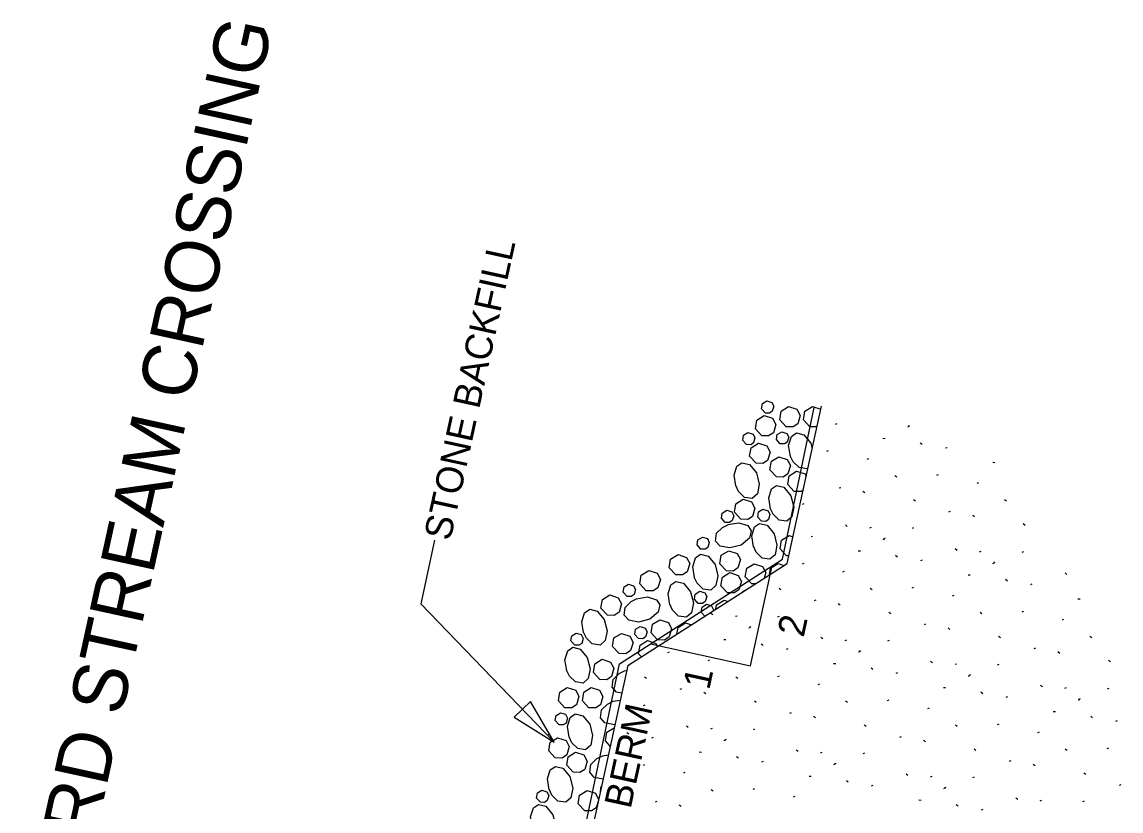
# Model space of a CAD drawing. Extents: x 2126110 to 2128246, y 1804858 to 1811658.
# Drawn here: x 2126689.8 to 2126892.6, y 1806594 to 1806739.6 of the extents above; entities that cross this region are included whole.
import ezdxf

# ---------------------------------------------------------------- set-up
doc = ezdxf.new("R2010")
doc.units = 0
doc.layers.add('1', color=7, linetype='Continuous')

msp = doc.modelspace()

# ---------------------------------------------------------------- linework, layer by layer
at = {"layer": '1'}
for p, q in [((2126830.13, 1806640.44), (2126835.96, 1806668.43)), ((2126830.97, 1806639.65), (2126837.31, 1806668.67)), ((2126839.93, 1806665.39), (2126840.23, 1806665.51)), ((2126853.24, 1806664.89), (2126853.54, 1806665)), ((2126853.37, 1806665.04), (2126853.58, 1806665.12)), ((2126848.65, 1806662.79), (2126849.05, 1806662.75)), ((2126855.89, 1806661.63), (2126855.54, 1806661.88)), ((2126838.34, 1806660.37), (2126838.64, 1806660.49)), ((2126860.2, 1806660.97), (2126860.49, 1806661.08)), ((2126845.78, 1806658.92), (2126846.08, 1806659.03)), ((2126868.91, 1806658.36), (2126869.31, 1806658.32)), ((2126851.2, 1806655.56), (2126850.85, 1806655.82)), ((2126858.61, 1806655.94), (2126858.9, 1806656.06)), ((2126840.58, 1806653.6), (2126840.88, 1806653.71)), ((2126866.04, 1806654.49), (2126866.34, 1806654.61)), ((2126845.31, 1806652.71), (2126844.95, 1806652.97)), ((2126854.64, 1806651.13), (2126854.29, 1806651.39)), ((2126871.46, 1806651.13), (2126871.11, 1806651.39)), ((2126833.83, 1806650.59), (2126834.13, 1806650.71)), ((2126860.84, 1806649.17), (2126861.14, 1806649.29)), ((2126865.57, 1806648.29), (2126865.22, 1806648.54)), ((2126842.09, 1806646.51), (2126841.73, 1806646.77)), ((2126846.24, 1806646.26), (2126846.54, 1806646.38)), ((2126854.09, 1806646.16), (2126854.39, 1806646.28)), ((2126874.91, 1806646.7), (2126874.55, 1806646.96)), ((2126765.94, 1806643.94), (2126763.38, 1806632.22)), ((2126835.39, 1806644.62), (2126835.69, 1806644.73)), ((2126848.7, 1806644.11), (2126849, 1806644.23)), ((2126848.83, 1806644.26), (2126849.13, 1806644.38)), ((2126831.28, 1806641.09), (2126830.9, 1806641.1)), ((2126844.11, 1806642.01), (2126844.51, 1806641.97)), ((2126851.35, 1806640.85), (2126851, 1806641.11)), ((2126862.35, 1806642.08), (2126862, 1806642.34)), ((2126866.5, 1806641.83), (2126866.8, 1806641.95)), ((2126874.35, 1806641.73), (2126874.65, 1806641.85)), ((2126800.03, 1806621.15), (2126830.13, 1806640.44)), ((2126801.61, 1806620.82), (2126830.97, 1806639.65)), ((2126824.21, 1806620.79), (2126828.24, 1806639.23)), ((2126833.8, 1806639.59), (2126834.1, 1806639.71)), ((2126855.65, 1806640.19), (2126855.95, 1806640.31)), ((2126868.96, 1806639.68), (2126869.26, 1806639.8)), ((2126869.1, 1806639.83), (2126869.39, 1806639.95)), ((2126841.24, 1806638.14), (2126841.54, 1806638.25)), ((2126864.37, 1806637.58), (2126864.77, 1806637.54)), ((2126882.61, 1806637.65), (2126882.26, 1806637.91)), ((2126825.08, 1806635.88), (2126824.46, 1806635.89)), ((2126829.84, 1806634.78), (2126829.49, 1806635.04)), ((2126846.66, 1806634.78), (2126846.31, 1806635.04)), ((2126854.07, 1806635.16), (2126854.36, 1806635.28)), ((2126871.62, 1806636.42), (2126871.26, 1806636.68)), ((2126875.92, 1806635.76), (2126876.22, 1806635.88)), ((2126836.04, 1806632.82), (2126836.34, 1806632.93)), ((2126861.5, 1806633.71), (2126861.8, 1806633.83)), ((2126884.63, 1806633.15), (2126885.03, 1806633.11)), ((2126787.99, 1806606.68), (2126763.38, 1806632.22)), ((2126840.76, 1806631.94), (2126840.41, 1806632.19)), ((2126817.28, 1806630.16), (2126816.93, 1806630.42)), ((2126821.44, 1806629.91), (2126821.74, 1806630.03)), ((2126829.29, 1806629.81), (2126829.59, 1806629.93)), ((2126850.1, 1806630.35), (2126849.75, 1806630.61)), ((2126866.92, 1806630.36), (2126866.57, 1806630.61)), ((2126874.33, 1806630.74), (2126874.63, 1806630.85)), ((2126881.76, 1806629.28), (2126882.06, 1806629.4)), ((2126823.89, 1806627.76), (2126824.19, 1806627.88)), ((2126824.03, 1806627.91), (2126824.33, 1806628.03)), ((2126856.3, 1806628.39), (2126856.6, 1806628.51)), ((2126861.03, 1806627.51), (2126860.67, 1806627.77)), ((2126805.76, 1806624.82), (2126824.21, 1806620.79)), ((2126819.3, 1806625.66), (2126819.7, 1806625.62)), ((2126837.55, 1806625.73), (2126837.19, 1806625.99)), ((2126841.7, 1806625.48), (2126842, 1806625.6)), ((2126849.55, 1806625.38), (2126849.85, 1806625.5)), ((2126870.37, 1806625.92), (2126870.01, 1806626.18)), ((2126887.18, 1806625.93), (2126886.83, 1806626.19)), ((2126809, 1806623.24), (2126809.3, 1806623.36)), ((2126826.55, 1806624.5), (2126826.2, 1806624.76)), ((2126830.85, 1806623.84), (2126831.15, 1806623.95)), ((2126844.16, 1806623.33), (2126844.45, 1806623.45)), ((2126844.29, 1806623.48), (2126844.59, 1806623.6)), ((2126876.57, 1806623.96), (2126876.87, 1806624.08)), ((2126881.29, 1806623.08), (2126880.94, 1806623.34)), ((2126793.9, 1806591.8), (2126800.03, 1806621.15)), ((2126801.61, 1806620.82), (2126795.26, 1806591.77)), ((2126816.44, 1806621.79), (2126816.73, 1806621.9)), ((2126839.57, 1806621.23), (2126839.97, 1806621.19)), ((2126857.81, 1806621.3), (2126857.46, 1806621.56)), ((2126861.96, 1806621.06), (2126862.26, 1806621.17)), ((2126869.81, 1806620.96), (2126870.11, 1806621.07)), ((2126890.63, 1806621.49), (2126890.28, 1806621.75)), ((2126801, 1806619.88), (2126801.42, 1806619.94)), ((2126829.26, 1806618.81), (2126829.56, 1806618.93)), ((2126846.81, 1806620.07), (2126846.46, 1806620.33)), ((2126851.11, 1806619.41), (2126851.41, 1806619.53)), ((2126864.42, 1806618.9), (2126864.72, 1806619.02)), ((2126864.56, 1806619.06), (2126864.85, 1806619.17)), ((2126805.04, 1806618.43), (2126804.69, 1806618.69)), ((2126821.86, 1806618.43), (2126821.5, 1806618.69)), ((2126836.7, 1806617.36), (2126837, 1806617.48)), ((2126859.83, 1806616.8), (2126860.23, 1806616.76)), ((2126878.07, 1806616.88), (2126877.72, 1806617.13)), ((2126882.23, 1806616.63), (2126882.53, 1806616.75)), ((2126811.24, 1806616.47), (2126811.54, 1806616.58)), ((2126815.96, 1806615.58), (2126815.61, 1806615.84)), ((2126867.08, 1806615.64), (2126866.72, 1806615.9)), ((2126871.38, 1806614.98), (2126871.68, 1806615.1)), ((2126884.82, 1806614.63), (2126885.12, 1806614.74)), ((2126890.08, 1806616.53), (2126890.37, 1806616.64)), ((2126798.83, 1806614.23), (2126800.22, 1806614.46)), ((2126804.48, 1806613.46), (2126804.78, 1806613.58)), ((2126825.3, 1806614), (2126824.95, 1806614.26)), ((2126842.12, 1806614), (2126841.77, 1806614.26)), ((2126849.52, 1806614.39), (2126849.82, 1806614.5)), ((2126856.96, 1806612.93), (2126857.26, 1806613.05)), ((2126884.68, 1806614.48), (2126884.98, 1806614.59)), ((2126831.5, 1806612.04), (2126831.8, 1806612.16)), ((2126836.22, 1806611.16), (2126835.87, 1806611.42)), ((2126880.09, 1806612.38), (2126880.49, 1806612.33)), ((2126887.34, 1806611.21), (2126886.99, 1806611.47)), ((2126891.64, 1806610.55), (2126891.94, 1806610.67)), ((2126812.74, 1806609.38), (2126812.39, 1806609.64)), ((2126816.9, 1806609.13), (2126817.2, 1806609.25)), ((2126824.75, 1806609.03), (2126825.05, 1806609.15)), ((2126845.56, 1806609.57), (2126845.21, 1806609.83)), ((2126862.38, 1806609.58), (2126862.03, 1806609.84)), ((2126869.79, 1806609.96), (2126870.09, 1806610.08)), ((2126877.22, 1806608.5), (2126877.52, 1806608.62)), ((2126801.75, 1806608.15), (2126801.39, 1806608.4)), ((2126806.05, 1806607.49), (2126806.35, 1806607.6)), ((2126819.35, 1806606.98), (2126819.65, 1806607.1)), ((2126819.49, 1806607.13), (2126819.79, 1806607.25)), ((2126851.76, 1806607.61), (2126852.06, 1806607.73)), ((2126856.49, 1806606.73), (2126856.13, 1806606.99)), ((2126814.76, 1806604.88), (2126815.16, 1806604.84)), ((2126833, 1806604.95), (2126832.65, 1806605.21)), ((2126837.16, 1806604.71), (2126837.46, 1806604.82)), ((2126845.01, 1806604.6), (2126845.31, 1806604.72)), ((2126865.83, 1806605.14), (2126865.47, 1806605.4)), ((2126882.64, 1806605.15), (2126882.29, 1806605.41)), ((2126890.05, 1806605.53), (2126890.35, 1806605.65)), ((2126796.88, 1806604.16), (2126798.01, 1806604.35)), ((2126804.46, 1806602.46), (2126804.76, 1806602.58)), ((2126822.01, 1806603.72), (2126821.66, 1806603.98)), ((2126826.31, 1806603.06), (2126826.61, 1806603.18)), ((2126839.62, 1806602.55), (2126839.91, 1806602.67)), ((2126839.75, 1806602.7), (2126840.05, 1806602.82)), ((2126872.03, 1806603.18), (2126872.32, 1806603.3)), ((2126876.75, 1806602.3), (2126876.4, 1806602.56)), ((2126811.9, 1806601.01), (2126812.19, 1806601.13)), ((2126853.27, 1806600.52), (2126852.92, 1806600.78)), ((2126886.09, 1806600.72), (2126885.74, 1806600.97)), ((2126835.03, 1806600.45), (2126835.43, 1806600.41)), ((2126842.27, 1806599.29), (2126841.92, 1806599.55)), ((2126846.57, 1806598.63), (2126846.87, 1806598.75)), ((2126857.42, 1806600.28), (2126857.72, 1806600.39)), ((2126865.27, 1806600.18), (2126865.57, 1806600.29)), ((2126892.29, 1806598.76), (2126892.59, 1806598.87)), ((2126800.5, 1806597.65), (2126800.15, 1806597.91)), ((2126817.32, 1806597.65), (2126816.96, 1806597.91)), ((2126824.72, 1806598.04), (2126825.02, 1806598.15)), ((2126832.16, 1806596.58), (2126832.46, 1806596.7)), ((2126859.88, 1806598.13), (2126860.18, 1806598.24)), ((2126860.02, 1806598.28), (2126860.31, 1806598.39)), ((2126806.7, 1806595.69), (2126807, 1806595.81)), ((2126811.42, 1806594.81), (2126811.07, 1806595.07)), ((2126855.29, 1806596.03), (2126855.69, 1806595.98)), ((2126862.53, 1806594.86), (2126862.18, 1806595.12)), ((2126873.53, 1806596.1), (2126873.18, 1806596.36)), ((2126877.69, 1806595.85), (2126877.98, 1806595.97)), ((2126885.53, 1806595.75), (2126885.83, 1806595.87)), ((2126866.84, 1806594.2), (2126867.13, 1806594.32))]:
    msp.add_line(p, q, dxfattribs=at)
for points in [[(2126826.97, 1806667.42), (2126826.26, 1806668.19), (2126826.41, 1806669.15), (2126827.23, 1806669.66), (2126828.16, 1806669.35), (2126828.52, 1806668.66), (2126828.25, 1806667.75), (2126827.73, 1806667.4), (2126826.97, 1806667.42)], [(2126830.8, 1806664.89), (2126829.61, 1806666.18), (2126829.87, 1806667.77), (2126831.24, 1806668.62), (2126832.79, 1806668.11), (2126833.39, 1806666.96), (2126832.94, 1806665.43), (2126832.07, 1806664.86), (2126830.8, 1806664.89)], [(2126835.2, 1806664.9), (2126834.01, 1806666.19), (2126834.26, 1806667.78), (2126835.64, 1806668.63), (2126837.19, 1806668.12), (2126837.19, 1806668.12)], [(2126826.3, 1806663.24), (2126825.12, 1806664.53), (2126825.37, 1806666.13), (2126826.74, 1806666.97), (2126828.3, 1806666.47), (2126828.89, 1806665.32), (2126828.44, 1806663.79), (2126827.57, 1806663.21), (2126826.3, 1806663.24)], [(2126823.5, 1806661.59), (2126822.79, 1806662.37), (2126822.94, 1806663.32), (2126823.76, 1806663.83), (2126824.7, 1806663.53), (2126825.05, 1806662.84), (2126824.78, 1806661.92), (2126824.26, 1806661.58), (2126823.5, 1806661.59)], [(2126829.73, 1806661.74), (2126829.02, 1806662.51), (2126829.17, 1806663.47), (2126829.99, 1806663.98), (2126830.93, 1806663.67), (2126831.28, 1806662.98), (2126831.01, 1806662.07), (2126830.49, 1806661.72), (2126829.73, 1806661.74)], [(2126831.58, 1806659.44), (2126831.25, 1806661.45), (2126831.77, 1806663.11), (2126832.71, 1806663.75), (2126834.08, 1806663.42), (2126835.37, 1806661.86), (2126835.61, 1806660.91)], [(2126836.48, 1806664.88), (2126836.47, 1806664.87), (2126835.2, 1806664.9)], [(2126825.25, 1806658.15), (2126824.06, 1806659.44), (2126824.32, 1806661.03), (2126825.69, 1806661.88), (2126827.24, 1806661.37), (2126827.84, 1806660.22), (2126827.39, 1806658.69), (2126826.52, 1806658.12), (2126825.25, 1806658.15)], [(2126829, 1806655.63), (2126827.81, 1806656.93), (2126828.07, 1806658.52), (2126829.44, 1806659.36), (2126830.99, 1806658.86), (2126831.59, 1806657.71), (2126831.14, 1806656.18), (2126830.27, 1806655.61), (2126829, 1806655.63)], [(2126834.83, 1806657.33), (2126834.62, 1806657.13), (2126833.18, 1806657.35), (2126832.09, 1806658.44), (2126831.55, 1806659.53)], [(2126821.52, 1806653.96), (2126821.2, 1806655.96), (2126821.71, 1806657.62), (2126822.65, 1806658.26), (2126824.02, 1806657.93), (2126825.32, 1806656.37), (2126825.85, 1806654.28), (2126825.49, 1806652.49), (2126824.56, 1806651.65), (2126823.12, 1806651.86), (2126822.03, 1806652.95), (2126821.49, 1806654.04)], [(2126832.3, 1806652.97), (2126831.12, 1806654.26), (2126831.37, 1806655.85), (2126832.74, 1806656.7), (2126834.3, 1806656.19), (2126834.5, 1806655.8)], [(2126827.9, 1806649.76), (2126827.58, 1806651.76), (2126828.09, 1806653.42), (2126829.03, 1806654.06), (2126830.4, 1806653.73), (2126831.69, 1806652.17), (2126832.23, 1806650.08), (2126831.87, 1806648.29), (2126830.94, 1806647.45), (2126829.5, 1806647.66), (2126828.41, 1806648.75), (2126827.87, 1806649.84)], [(2126822.44, 1806647.81), (2126821.26, 1806649.1), (2126821.51, 1806650.69), (2126822.88, 1806651.54), (2126824.44, 1806651.03), (2126825.03, 1806649.88), (2126824.58, 1806648.35), (2126823.71, 1806647.78), (2126822.44, 1806647.81)], [(2126833.92, 1806653.18), (2126833.57, 1806652.94), (2126832.3, 1806652.97)], [(2126819.57, 1806647.24), (2126818.86, 1806648.01), (2126819.01, 1806648.97), (2126819.83, 1806649.48), (2126820.76, 1806649.17), (2126821.12, 1806648.48), (2126820.85, 1806647.57), (2126820.33, 1806647.22), (2126819.57, 1806647.24)], [(2126826.27, 1806647.44), (2126825.55, 1806648.22), (2126825.71, 1806649.17), (2126826.53, 1806649.68), (2126827.46, 1806649.38), (2126827.82, 1806648.69), (2126827.55, 1806647.77), (2126827.03, 1806647.42), (2126826.27, 1806647.44)], [(2126820.07, 1806646.84), (2126822.07, 1806647.17), (2126823.73, 1806646.65), (2126824.37, 1806645.71), (2126824.04, 1806644.34), (2126822.48, 1806643.05), (2126820.39, 1806642.52), (2126818.6, 1806642.87), (2126817.75, 1806643.8), (2126817.97, 1806645.24), (2126819.06, 1806646.33), (2126820.15, 1806646.87)], [(2126824.79, 1806642.75), (2126824.46, 1806644.75), (2126824.97, 1806646.41), (2126825.91, 1806647.05), (2126827.28, 1806646.72), (2126828.58, 1806645.16), (2126829.11, 1806643.07), (2126828.75, 1806641.28), (2126827.82, 1806640.43), (2126826.38, 1806640.65), (2126825.29, 1806641.74), (2126824.75, 1806642.83)], [(2126815.07, 1806642.3), (2126814.36, 1806643.08), (2126814.51, 1806644.03), (2126815.34, 1806644.54), (2126816.27, 1806644.24), (2126816.63, 1806643.55), (2126816.36, 1806642.63), (2126815.84, 1806642.29), (2126815.08, 1806642.3)], [(2126830.89, 1806641.1), (2126829.71, 1806642.39), (2126829.96, 1806643.98), (2126831.33, 1806644.83), (2126832.05, 1806644.6)], [(2126810.43, 1806637.57), (2126809.24, 1806638.86), (2126809.49, 1806640.45), (2126810.87, 1806641.3), (2126812.42, 1806640.79), (2126813.02, 1806639.65), (2126812.57, 1806638.12), (2126811.7, 1806637.54), (2126810.43, 1806637.57)], [(2126813.9, 1806637.05), (2126813.57, 1806639.05), (2126814.08, 1806640.71), (2126815.02, 1806641.35), (2126816.39, 1806641.02), (2126817.69, 1806639.46), (2126818.22, 1806637.37), (2126817.86, 1806635.58), (2126816.93, 1806634.73), (2126815.49, 1806634.95), (2126814.4, 1806636.04), (2126813.86, 1806637.13)], [(2126819.77, 1806638.29), (2126818.59, 1806639.58), (2126818.84, 1806641.17), (2126820.21, 1806642.02), (2126821.77, 1806641.52), (2126822.36, 1806640.37), (2126821.91, 1806638.84), (2126821.04, 1806638.26), (2126819.77, 1806638.29)], [(2126824.46, 1806635.89), (2126823.27, 1806637.18), (2126823.53, 1806638.77), (2126824.9, 1806639.62), (2126826.46, 1806639.11), (2126827.05, 1806637.97), (2126826.75, 1806636.95)], [(2126827.73, 1806637.58), (2126827.93, 1806638.78), (2126829.3, 1806639.63), (2126830.38, 1806639.28)], [(2126805, 1806634.63), (2126803.81, 1806635.92), (2126804.06, 1806637.51), (2126805.44, 1806638.36), (2126806.99, 1806637.85), (2126807.59, 1806636.7), (2126807.14, 1806635.17), (2126806.27, 1806634.6), (2126805, 1806634.63)], [(2126819.96, 1806634.25), (2126818.78, 1806635.54), (2126819.03, 1806637.13), (2126820.41, 1806637.98), (2126821.96, 1806637.47), (2126822.56, 1806636.32), (2126822.1, 1806634.79), (2126821.24, 1806634.22), (2126819.97, 1806634.25)], [(2126801.46, 1806633.6), (2126800.75, 1806634.37), (2126800.9, 1806635.33), (2126801.72, 1806635.84), (2126802.65, 1806635.53), (2126803.01, 1806634.85), (2126802.74, 1806633.93), (2126802.22, 1806633.58), (2126801.46, 1806633.6)], [(2126809.35, 1806632.05), (2126809.03, 1806634.05), (2126809.54, 1806635.71), (2126810.48, 1806636.35), (2126811.85, 1806636.02), (2126813.15, 1806634.46), (2126813.68, 1806632.37), (2126813.32, 1806630.58), (2126812.39, 1806629.74), (2126810.95, 1806629.95), (2126809.86, 1806631.04), (2126809.32, 1806632.13)], [(2126822.83, 1806634.43), (2126822.83, 1806634.47), (2126823.66, 1806634.98), (2126823.67, 1806634.97)], [(2126797.83, 1806630.12), (2126796.64, 1806631.41), (2126796.9, 1806633.01), (2126798.27, 1806633.85), (2126799.82, 1806633.35), (2126800.42, 1806632.2), (2126799.97, 1806630.67), (2126799.1, 1806630.09), (2126797.83, 1806630.12)], [(2126803.22, 1806633.16), (2126805.22, 1806633.49), (2126806.88, 1806632.97), (2126807.52, 1806632.03), (2126807.19, 1806630.66), (2126805.63, 1806629.37), (2126803.54, 1806628.84), (2126801.75, 1806629.2), (2126800.9, 1806630.13), (2126801.12, 1806631.56), (2126802.21, 1806632.65), (2126803.3, 1806633.19)], [(2126814.58, 1806632.29), (2126813.87, 1806633.07), (2126814.02, 1806634.03), (2126814.85, 1806634.53), (2126815.78, 1806634.23), (2126816.14, 1806633.54), (2126815.86, 1806632.62), (2126815.34, 1806632.28), (2126814.58, 1806632.3)], [(2126793.43, 1806626.91), (2126793.1, 1806628.91), (2126793.62, 1806630.57), (2126794.56, 1806631.21), (2126795.93, 1806630.88), (2126797.22, 1806629.32), (2126797.76, 1806627.23), (2126797.4, 1806625.44), (2126796.47, 1806624.6), (2126795.03, 1806624.81), (2126793.94, 1806625.9), (2126793.4, 1806626.99)], [(2126815.81, 1806629.93), (2126815.13, 1806630.66), (2126815.29, 1806631.62), (2126816.11, 1806632.13), (2126817.04, 1806631.82), (2126817.4, 1806631.13), (2126817.33, 1806630.91)], [(2126817.85, 1806631.24), (2126817.98, 1806632.03), (2126819.35, 1806632.88), (2126820.05, 1806632.65)], [(2126807.07, 1806625.56), (2126805.89, 1806626.85), (2126806.14, 1806628.44), (2126807.51, 1806629.29), (2126809.07, 1806628.78), (2126809.66, 1806627.63), (2126809.21, 1806626.1), (2126808.34, 1806625.53), (2126807.07, 1806625.56)], [(2126791.8, 1806624.59), (2126791.08, 1806625.37), (2126791.24, 1806626.32), (2126792.06, 1806626.83), (2126792.99, 1806626.53), (2126793.35, 1806625.84), (2126793.08, 1806624.92), (2126792.56, 1806624.58), (2126791.8, 1806624.59)], [(2126803.58, 1806625.79), (2126802.87, 1806626.57), (2126803.02, 1806627.52), (2126803.84, 1806628.03), (2126804.77, 1806627.73), (2126805.13, 1806627.04), (2126804.86, 1806626.12), (2126804.34, 1806625.78), (2126803.58, 1806625.79)], [(2126810.65, 1806626.62), (2126810.85, 1806627.87), (2126812.22, 1806628.72), (2126813.35, 1806628.35)], [(2126799.97, 1806623.04), (2126798.78, 1806624.33), (2126799.03, 1806625.92), (2126800.41, 1806626.77), (2126801.96, 1806626.26), (2126802.56, 1806625.11), (2126802.11, 1806623.58), (2126801.24, 1806623.01), (2126799.97, 1806623.04)], [(2126804.11, 1806622.42), (2126803.59, 1806622.99), (2126803.84, 1806624.58), (2126805.21, 1806625.43), (2126806.77, 1806624.92), (2126807.07, 1806624.33)], [(2126790.31, 1806619.9), (2126789.99, 1806621.9), (2126790.5, 1806623.56), (2126791.44, 1806624.2), (2126792.81, 1806623.87), (2126794.11, 1806622.31), (2126794.64, 1806620.22), (2126794.28, 1806618.43), (2126793.35, 1806617.59), (2126791.91, 1806617.8), (2126790.82, 1806618.89), (2126790.28, 1806619.98)], [(2126796.42, 1806618.25), (2126795.24, 1806619.54), (2126795.49, 1806621.13), (2126796.86, 1806621.98), (2126798.42, 1806621.47), (2126799.01, 1806620.33), (2126798.56, 1806618.8), (2126797.69, 1806618.22), (2126796.42, 1806618.25)], [(2126800.49, 1806615.72), (2126799.53, 1806615.91), (2126798.69, 1806616.84), (2126798.9, 1806618.28), (2126799.99, 1806619.37), (2126801.08, 1806619.91)], [(2126789.99, 1806613.04), (2126788.8, 1806614.33), (2126789.06, 1806615.93), (2126790.43, 1806616.77), (2126791.98, 1806616.27), (2126792.58, 1806615.12), (2126792.13, 1806613.59), (2126791.26, 1806613.01), (2126789.99, 1806613.04)], [(2126794.39, 1806613.05), (2126793.2, 1806614.34), (2126793.46, 1806615.94), (2126794.83, 1806616.78), (2126796.38, 1806616.28), (2126796.98, 1806615.13), (2126796.53, 1806613.6), (2126795.66, 1806613.02), (2126794.39, 1806613.05)], [(2126799.23, 1806609.93), (2126799.15, 1806609.91), (2126797.36, 1806610.26), (2126796.52, 1806611.19), (2126796.73, 1806612.63), (2126797.82, 1806613.72), (2126798.91, 1806614.26)], [(2126788.92, 1806609.89), (2126788.21, 1806610.67), (2126788.36, 1806611.62), (2126789.19, 1806612.13), (2126790.12, 1806611.83), (2126790.48, 1806611.14), (2126790.2, 1806610.22), (2126789.68, 1806609.88), (2126788.92, 1806609.89)], [(2126790.77, 1806607.6), (2126790.45, 1806609.6), (2126790.96, 1806611.26), (2126791.9, 1806611.9), (2126793.27, 1806611.58), (2126794.56, 1806610.01), (2126795.1, 1806607.92), (2126794.74, 1806606.13), (2126793.81, 1806605.29), (2126792.37, 1806605.5), (2126791.28, 1806606.59), (2126790.74, 1806607.69)], [(2126798.36, 1806605.96), (2126797.47, 1806606.92), (2126797.73, 1806608.51), (2126799.1, 1806609.36), (2126799.1, 1806609.36)], [(2126787.01, 1806608.41), (2126787.03, 1806608.38), (2126786.93, 1806608.03)], [(2126788.19, 1806603.79), (2126787.01, 1806605.08), (2126787.26, 1806606.67), (2126788.63, 1806607.52), (2126790.19, 1806607.01), (2126790.78, 1806605.87), (2126790.33, 1806604.34), (2126789.46, 1806603.76), (2126788.19, 1806603.79)], [(2126791.49, 1806601.13), (2126790.31, 1806602.42), (2126790.56, 1806604.01), (2126791.93, 1806604.86), (2126793.49, 1806604.35), (2126794.08, 1806603.2), (2126793.63, 1806601.67), (2126792.76, 1806601.1), (2126791.49, 1806601.13)], [(2126797.03, 1806599.88), (2126795.41, 1806600.2), (2126794.57, 1806601.13), (2126794.78, 1806602.57), (2126795.87, 1806603.66), (2126796.96, 1806604.2)], [(2126787.1, 1806597.91), (2126786.77, 1806599.92), (2126787.28, 1806601.58), (2126788.22, 1806602.21), (2126789.59, 1806601.89), (2126790.89, 1806600.33), (2126791.42, 1806598.23), (2126791.06, 1806596.45), (2126790.13, 1806595.6), (2126788.69, 1806595.82), (2126787.6, 1806596.91), (2126787.06, 1806598)], [(2126796.54, 1806597.62), (2126796.68, 1806598.53), (2126796.74, 1806598.57)], [(2126785.46, 1806595.6), (2126784.75, 1806596.37), (2126784.9, 1806597.33), (2126785.72, 1806597.83), (2126786.66, 1806597.53), (2126787.01, 1806596.84), (2126786.74, 1806595.92), (2126786.22, 1806595.58), (2126785.46, 1806595.6)], [(2126793.63, 1806594.04), (2126792.44, 1806595.33), (2126792.7, 1806596.92), (2126794.07, 1806597.77), (2126795.62, 1806597.26), (2126796.21, 1806596.13)], [(2126783.98, 1806590.9), (2126783.65, 1806592.9), (2126784.17, 1806594.57), (2126785.11, 1806595.2), (2126786.48, 1806594.88), (2126787.77, 1806593.31), (2126788.3, 1806591.22), (2126787.94, 1806589.44), (2126787.01, 1806588.59), (2126785.58, 1806588.8), (2126784.49, 1806589.89), (2126783.95, 1806590.99)], [(2126796.17, 1806595.96), (2126795.77, 1806594.59), (2126794.9, 1806594.01), (2126793.63, 1806594.04)]]:
    msp.add_lwpolyline(points, dxfattribs=at)
msp.add_lwpolyline([(2126780.62, 1806611.29), (2126787.99, 1806606.68), (2126783.65, 1806614.22)], close=True, dxfattribs=at)

# ---------------------------------------------------------------- texts
for s, height, p in [('FORD STREAM CROSSING', 10.0002, (2126699.35, 1806570.69)), ('STONE BACKFILL', 5, (2126768.83, 1806643.69)), ('2', 5, (2126834.02, 1806625.89)), ('1', 5, (2126816.6, 1806616.19)), ('BERM', 5, (2126802.09, 1806594.23))]:
    msp.add_text(s, height=height, rotation=77.6736, dxfattribs=at).set_placement(p)

doc.saveas('drawing.dxf')
